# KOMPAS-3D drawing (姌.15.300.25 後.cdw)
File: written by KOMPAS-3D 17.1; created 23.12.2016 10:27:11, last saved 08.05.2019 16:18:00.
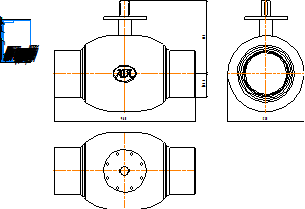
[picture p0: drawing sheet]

Sheet 1: A4, portrait

Title block, sheet 1: name: КШ.15.300.25 сс; material: Внимание! Данный продукт является объектом авторского права ООО «Торговый Дом АДЛ». / Запрещается изменение, копирование, распространение / (в том числе путем копирования на другие сайты и ресурсы в Интернете) / или любое иное использование информации и объектов без предварительного / согласия правообладателя (ООО «Торговый Дом АДЛ»).; sheets: 1; organisation: ООО "Торговый дом АДЛ"; sheet format: A4; stored path: C:\Users\tra\Desktop\2д чертежи\Шаровые краны БИВАЛ\КШ_Бивал_серия_14_15\KOMPAS_2D\КШ.15.300.25 сс.cdw

Views: Вид 1, Проекционный вид 2, Проекционный вид 3
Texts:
  Klimkovich
  ADL
Dimensions and other numbers on the sheet: 980; 505; 162,5; 530; 1:1; 1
